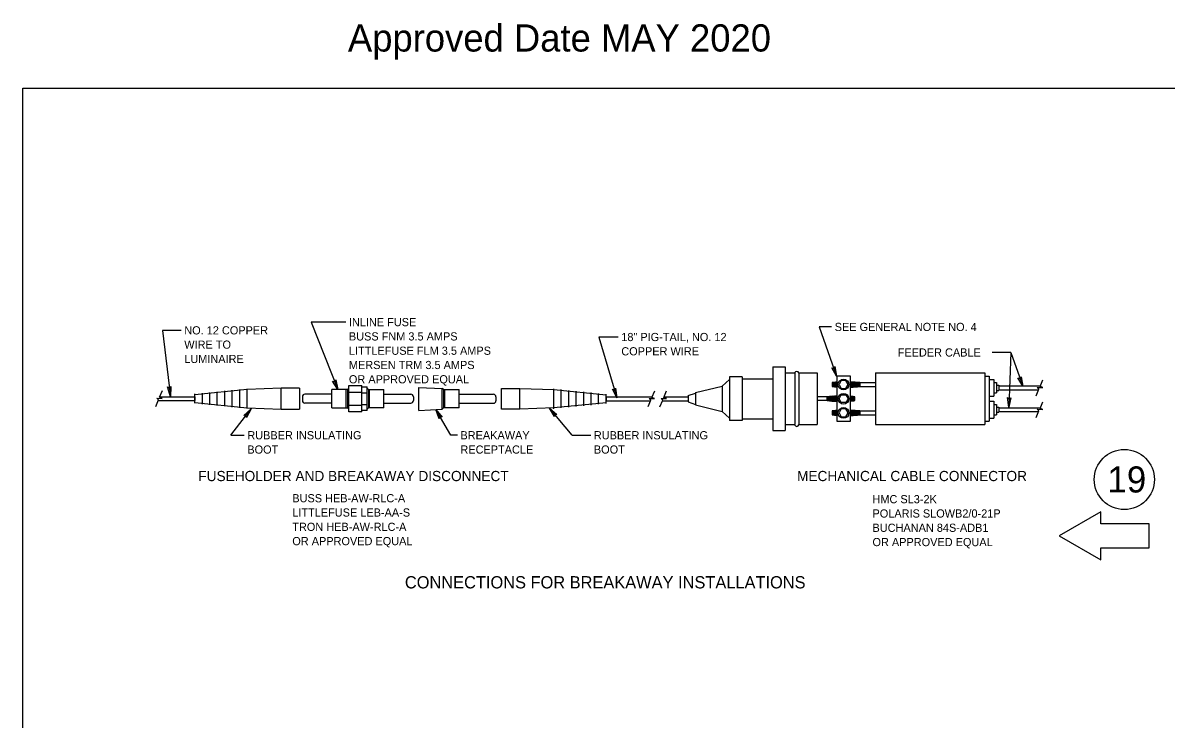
# Model space of a CAD drawing. Extents: x 99981 to 128681, y 99783 to 102182.
# Drawn here: x 125481 to 127161, y 101159 to 102182 of the extents above; entities that cross this region are included whole.
import ezdxf

# ---------------------------------------------------------------- set-up
doc = ezdxf.new("R2010")
doc.units = 0
for name, color, linetype in [('Default', 7, 'Continuous'), ('Level 1', 7, 'Continuous'), ('RD Lighting', 7, 'Continuous'), ('RD Standard Plans Active', 7, 'Continuous')]:
    doc.layers.add(name, color=color, linetype=linetype)

msp = doc.modelspace()

# ---------------------------------------------------------------- linework, layer by layer
at = {"layer": 'Default'}
msp.add_lwpolyline([(125481.4, 102086.3), (128681.1, 102086.3), (128681.1, 99886.7), (125481.4, 99886.7)], close=True, dxfattribs=at)
at = {"layer": 'Level 1'}
for p, q in [((125714, 101730.5), (125686.4, 101730.5)), ((125686.4, 101730.5), (125698.1, 101633)), ((125955.8, 101742.6), (125904.9, 101742.6)), ((125904.9, 101742.6), (125943.8, 101643.6)), ((126669.3, 101735.5), (126650.8, 101735.5)), ((126650.8, 101735.5), (126676.4, 101663.1)), ((126327.6, 101720.7), (126353.7, 101631.4)), ((126355.9, 101720.7), (126327.6, 101720.7)), ((126932.4, 101698), (126905, 101698)), ((126932.4, 101698), (126929.8, 101617.4)), ((126932.4, 101698), (126949.9, 101648.3)), ((126519.2, 101662), (126519.2, 101598.1)), ((126537.9, 101662), (126519.2, 101662)), ((126537.9, 101662), (126537.9, 101598.1)), ((126583, 101676.7), (126583, 101583.4)), ((126583, 101676.7), (126600.8, 101676.7)), ((126600.8, 101676.7), (126600.8, 101583.4)), ((126600.8, 101667.9), (126615, 101667.9)), ((126615, 101667.9), (126615, 101592.2)), ((126621, 101667.9), (126621, 101592.2)), ((126621, 101667.9), (126648.1, 101667.9)), ((126648.1, 101667.9), (126648.1, 101592.2)), ((126733.5, 101667.9), (126894.3, 101667.9)), ((126733.5, 101667.9), (126733.5, 101592.2)), ((126894.3, 101667.9), (126894.3, 101592.2)), ((126894.3, 101663.2), (126900.9, 101663.2)), ((126900.9, 101663.2), (126900.9, 101596.9)), ((125860.8, 101645.5), (125810.9, 101643.6)), ((125810.9, 101615.6), (125810.9, 101644.8)), ((125860.8, 101614.8), (125860.8, 101645.5)), ((125887.7, 101645.5), (125860.8, 101645.5)), ((125887.7, 101645.5), (125887.7, 101614.8)), ((125958.1, 101643.7), (125960, 101645.5)), ((125960, 101611), (125960, 101649.4)), ((125960, 101649.4), (125979.2, 101649.4)), ((125960, 101614.8), (125960, 101645.5)), ((125979.2, 101611), (125979.2, 101649.4)), ((125979.2, 101612.9), (125979.2, 101647.5)), ((125979.2, 101647.5), (125986.9, 101647.5)), ((125986.9, 101612.9), (125986.9, 101647.5)), ((125988.8, 101643.7), (125986.9, 101645.5)), ((126062.8, 101646.3), (126097.4, 101645.3)), ((126062.8, 101612.7), (126062.8, 101646.3)), ((126097.4, 101614.6), (126097.4, 101645.3)), ((126099.3, 101643.4), (126097.4, 101645.3)), ((126184.3, 101614.6), (126184.3, 101645.3)), ((126184.3, 101645.3), (126211.2, 101645.3)), ((126211.2, 101614.5), (126211.2, 101645.3)), ((126211.2, 101645.3), (126261.2, 101643.4)), ((126261.2, 101615.3), (126261.2, 101644.5)), ((126469.2, 101639.2), (126508.7, 101648.7)), ((126508.7, 101648.7), (126519.2, 101658.3)), ((126508.7, 101648.7), (126508.7, 101611.4)), ((126537.9, 101659.5), (126582.6, 101659.5)), ((126670.1, 101653.7), (126670.1, 101648)), ((126710.8, 101653.7), (126710.8, 101648)), ((126710.8, 101653.7), (126733.6, 101653.7)), ((126710.8, 101648), (126733.6, 101648)), ((126900.9, 101658.4), (126907.6, 101658.4)), ((126907.6, 101658.4), (126907.6, 101633.8)), ((126907.6, 101653.7), (126911.3, 101653.7)), ((126911.3, 101653.7), (126911.3, 101638.6)), ((126911.3, 101649.9), (126915.1, 101649.9)), ((126915.1, 101649.9), (126915.1, 101642.3)), ((126915.1, 101649), (126975.8, 101649)), ((126973.8, 101644.2), (126971.4, 101646.7)), ((126971.4, 101646.7), (126979.3, 101646.4)), ((126975.4, 101648.1), (126979.5, 101657.8)), ((126979.3, 101646.4), (126975.4, 101648.1)), ((125676.6, 101618.6), (125680.6, 101628.3)), ((125680.6, 101628.3), (125678.2, 101630.8)), ((125678.2, 101630.8), (125686.1, 101630.5)), ((125682.2, 101632.2), (125686.3, 101641.9)), ((125686.1, 101630.5), (125682.2, 101632.2)), ((125682.6, 101633), (125734.1, 101633)), ((125810.9, 101643.6), (125734.1, 101635.9)), ((125734.1, 101623.3), (125734.1, 101637.1)), ((125734.1, 101633), (125734.1, 101627.3)), ((125734.1, 101627.3), (125734.1, 101633)), ((125745, 101622.1), (125745, 101638.2)), ((125756, 101621.1), (125756, 101639.3)), ((125767, 101620), (125767, 101640.4)), ((125777.9, 101618.9), (125777.9, 101641.5)), ((125788.9, 101617.8), (125788.9, 101642.6)), ((125799.9, 101616.7), (125799.9, 101643.6)), ((125891.9, 101633), (125891.9, 101627.3)), ((125935.3, 101636.8), (125895.7, 101636.8)), ((125956.1, 101643.7), (125935.3, 101643.6)), ((125935.3, 101616.7), (125935.3, 101643.6)), ((125958.1, 101643.7), (125956.1, 101643.7)), ((125956.1, 101616.7), (125956.1, 101643.7)), ((125958.1, 101643.7), (125958.1, 101616.7)), ((125960, 101639.8), (125979.2, 101639.8)), ((125979.2, 101638.8), (125986.9, 101638.8)), ((125988.8, 101643.7), (125990.7, 101643.7)), ((125988.8, 101643.7), (125988.8, 101616.7)), ((125990.7, 101616.7), (125990.7, 101643.7)), ((125990.7, 101643.7), (126011.5, 101643.6)), ((126011.5, 101616.7), (126011.5, 101643.6)), ((126011.5, 101636.8), (126051.2, 101636.8)), ((126055, 101633), (126055, 101627.3)), ((126099.3, 101643.4), (126101.2, 101643.4)), ((126099.3, 101643.4), (126099.3, 101616.5)), ((126101.2, 101616.5), (126101.2, 101643.4)), ((126101.2, 101643.4), (126122, 101643.4)), ((126122, 101616.5), (126122, 101643.4)), ((126122, 101636.5), (126172.4, 101636.5)), ((126176.2, 101632.8), (126176.2, 101627.1)), ((126261.2, 101643.4), (126338, 101635.7)), ((126272.1, 101616.5), (126272.1, 101643.4)), ((126283.1, 101617.5), (126283.1, 101642.3)), ((126294.1, 101618.6), (126294.1, 101641.2)), ((126305.1, 101619.7), (126305.1, 101640.2)), ((126316, 101620.8), (126316, 101639)), ((126327, 101621.9), (126327, 101637.9)), ((126338, 101623), (126338, 101636.9)), ((126338, 101632.8), (126338, 101627.1)), ((126338, 101632.8), (126405.7, 101632.8)), ((126399.7, 101618.4), (126403.8, 101628.1)), ((126403.8, 101628.1), (126401.4, 101630.6)), ((126401.4, 101630.6), (126409.3, 101630.2)), ((126405.4, 101632), (126409.4, 101641.7)), ((126409.3, 101630.2), (126405.4, 101632)), ((126417.1, 101618.3), (126421.2, 101628)), ((126421.2, 101628), (126418.8, 101630.5)), ((126418.8, 101630.5), (126426.6, 101630.2)), ((126422.8, 101631.9), (126426.8, 101641.6)), ((126426.6, 101630.2), (126422.8, 101631.9)), ((126423.1, 101632.8), (126458.8, 101632.8)), ((126458.8, 101634.7), (126469.3, 101638.3)), ((126458.8, 101634.7), (126458.8, 101625.4)), ((126469.2, 101639.2), (126469.2, 101620.9)), ((126662.8, 101632.9), (126648.1, 101632.9)), ((126662.8, 101627.2), (126662.8, 101632.9)), ((126703.5, 101627.2), (126703.5, 101632.9)), ((126900.9, 101633.8), (126907.6, 101633.8)), ((126907.6, 101638.6), (126911.3, 101638.6)), ((126911.3, 101642.3), (126915.1, 101642.3)), ((126915.1, 101643.3), (126973.4, 101643.3)), ((126969.8, 101634.5), (126973.8, 101644.2)), ((125680.2, 101627.3), (125734.1, 101627.3)), ((125734.1, 101624.4), (125810.9, 101616.7)), ((125787, 101576.4), (125816.5, 101615.1)), ((125810.9, 101616.7), (125860.8, 101614.8)), ((125860.8, 101614.8), (125887.7, 101614.8)), ((125935.3, 101623.5), (125895.7, 101623.5)), ((125935.3, 101616.7), (125956.1, 101616.7)), ((125956.1, 101616.7), (125958.1, 101616.7)), ((125960, 101614.8), (125958.1, 101616.7)), ((125960, 101620.6), (125979.2, 101620.6)), ((125979.2, 101611), (125960, 101611)), ((125979.2, 101621.5), (125986.9, 101621.5)), ((125986.9, 101612.9), (125979.2, 101612.9)), ((125986.9, 101614.8), (125988.8, 101616.7)), ((125990.7, 101616.7), (125988.8, 101616.7)), ((126011.5, 101616.7), (125990.7, 101616.7)), ((126011.5, 101623.5), (126051.2, 101623.5)), ((126062.8, 101612.7), (126097.4, 101614.6)), ((126110.1, 101576.4), (126087.8, 101614.1)), ((126097.4, 101614.6), (126099.3, 101616.5)), ((126101.2, 101616.5), (126099.3, 101616.5)), ((126122, 101616.5), (126101.2, 101616.5)), ((126122, 101623.3), (126172.4, 101623.3)), ((126211.2, 101614.5), (126184.3, 101614.6)), ((126261.2, 101616.5), (126211.2, 101614.5)), ((126288.2, 101576.4), (126255, 101616.3)), ((126338, 101624.2), (126261.2, 101616.5)), ((126338, 101627.1), (126403.4, 101627.1)), ((126420.8, 101627.1), (126458.8, 101627.1)), ((126458.8, 101625.4), (126469.3, 101621.7)), ((126469.2, 101620.9), (126508.7, 101611.4)), ((126508.7, 101611.4), (126519.2, 101601.5)), ((126662.8, 101627.2), (126648.1, 101627.2)), ((126670.1, 101612.1), (126670.1, 101606.4)), ((126710.8, 101612.1), (126710.8, 101606.4)), ((126710.8, 101612.1), (126733.6, 101612.1)), ((126900.9, 101626.3), (126907.6, 101626.3)), ((126907.6, 101626.3), (126907.6, 101601.7)), ((126907.6, 101621.5), (126911.3, 101621.5)), ((126911.3, 101621.5), (126911.3, 101606.4)), ((126911.3, 101617.7), (126915.1, 101617.7)), ((126915.1, 101617.7), (126915.1, 101610.2)), ((126915.1, 101616.8), (126975.8, 101616.8)), ((126915.1, 101611.1), (126973.4, 101611.1)), ((126969.8, 101602.4), (126973.8, 101612.1)), ((126973.8, 101612.1), (126971.4, 101614.6)), ((126971.4, 101614.6), (126979.3, 101614.2)), ((126975.4, 101615.9), (126979.5, 101625.6)), ((126979.3, 101614.2), (126975.4, 101615.9)), ((126537.9, 101598.1), (126519.2, 101598.1)), ((126537.9, 101600.6), (126582.6, 101600.6)), ((126710.8, 101606.4), (126733.6, 101606.4)), ((126894.3, 101596.9), (126900.9, 101596.9)), ((126900.9, 101601.7), (126907.6, 101601.7)), ((126907.6, 101606.4), (126911.3, 101606.4)), ((126911.3, 101610.2), (126915.1, 101610.2)), ((126583, 101583.4), (126600.8, 101583.4)), ((126600.8, 101592.2), (126615, 101592.2)), ((126621, 101592.2), (126648.1, 101592.2)), ((126733.5, 101592.2), (126894.3, 101592.2)), ((125787, 101576.4), (125806.6, 101576.4)), ((126119.6, 101576.4), (126110.1, 101576.4)), ((126288.2, 101576.4), (126315.6, 101576.4))]:
    msp.add_line(p, q, dxfattribs=at)
for points in [[(126674, 101677.2), (126676.4, 101663.1), (126669.5, 101675.6), (126672.4, 101674.3)], [(126676.7, 101596.9), (126696.9, 101596.9), (126696.9, 101663.2), (126676.7, 101663.2)], [(126947.5, 101662.4), (126949.9, 101648.3), (126943, 101660.8), (126946, 101659.5)], [(125698.8, 101648.1), (125698.1, 101633), (125693.8, 101647.5), (125696.6, 101645.5)], [(125940.9, 101657.6), (125943.8, 101643.6), (125936.4, 101655.9), (125939.5, 101654.7)], [(126352, 101645.6), (126353.7, 101631.4), (126347.4, 101644.2), (126350.3, 101642.8)], [(126693.4, 101650.9), (126690.1, 101656.6), (126683.5, 101656.6), (126680.2, 101650.9), (126683.5, 101645.1), (126690.1, 101645.1)], [(126680.2, 101630), (126683.5, 101635.8), (126690.1, 101635.8), (126693.4, 101630), (126690.1, 101624.3), (126683.5, 101624.3)], [(126932.6, 101631.4), (126929.8, 101617.4), (126927.8, 101631.6), (126930.1, 101629.3)], [(125806.1, 101605.4), (125816.5, 101615.1), (125809.9, 101602.5), (125809.3, 101605.7)], [(126092.9, 101600.7), (126087.8, 101614.1), (126097, 101603.1), (126093.8, 101603.8)], [(126262.2, 101603.9), (126255, 101616.3), (126265.9, 101606.9), (126262.6, 101607.1)], [(126693.4, 101609.2), (126690.1, 101615), (126683.5, 101615), (126680.2, 101609.2), (126683.5, 101603.5), (126690.1, 101603.5)]]:
    msp.add_lwpolyline(points, close=True, dxfattribs=at)
for centre in [(126686.8, 101650.9), (126686.8, 101630), (126686.8, 101609.2)]:
    msp.add_circle(centre, 7.87, dxfattribs=at)
for centre, radius, start, end in [((126618, 101667.1), 3.13, 13.8187, 166.1813), ((126683.9, 101681), 35.3, 246.9234, 250.0588), ((126690.5, 101472.2), 182.6, 94.3078, 96.3947), ((126683.9, 101681), 34.2, 246.2968, 257.7799), ((126690.5, 101829.5), 182.6, 263.6053, 265.6922), ((126683.9, 101681), 31.3, 244.0184, 256.695), ((126683.9, 101681), 32.1, 244.8289, 257.172), ((126683.9, 101681), 32.9, 245.3688, 257.4424), ((126683.9, 101681), 33.5, 245.8941, 257.5753), ((126683.9, 101681), 34.8, 246.798, 253.7631), ((126683.9, 101681), 30.6, 243.617, 256.3872), ((126683.9, 101681), 30, 245.4513, 256.2262), ((126683.9, 101681), 29.3, 247.3871, 255.8534), ((126683.9, 101681), 28.7, 249.6525, 255.6032), ((126710.5, 101680.8), 34.2, 246.2968, 258.5078), ((126690.5, 101472.2), 182.6, 83.6053, 87.9783), ((126710.5, 101680.8), 31.9, 244.725, 270.432), ((126710.5, 101680.8), 33.4, 245.9109, 263.6185), ((126710.5, 101680.8), 34.8, 246.8841, 255.1625), ((126710.5, 101680.8), 35.4, 247.2896, 252.3204), ((126690.5, 101829.5), 182.6, 272.0217, 276.3947), ((126710.5, 101680.8), 36, 247.6656, 249.8244), ((126710.5, 101680.8), 30.1, 243.205, 270.432), ((126710.5, 101680.8), 31, 244.1545, 270.432), ((126710.5, 101680.8), 32.8, 245.5356, 270.432), ((126710.5, 101680.8), 29.2, 244.3604, 270.432), ((126710.5, 101680.8), 28.5, 246.8058, 270.432), ((126710.5, 101680.8), 27.9, 250.4487, 270.432), ((126710.5, 101680.8), 27.2, 257.6483, 270.432), ((125895.7, 101633), 3.78, 90, 180), ((126051.2, 101633), 3.78, 0, 90), ((126172.4, 101632.8), 3.78, 0, 90), ((126683.2, 101451.4), 182.6, 92.0217, 96.3947), ((126663.1, 101600.1), 32.8, 65.5356, 90.432), ((126663.1, 101600.1), 31.9, 64.725, 90.432), ((126663.1, 101600.1), 31, 64.1545, 90.432), ((126663.1, 101600.1), 30.1, 63.205, 90.432), ((126663.1, 101600.1), 29.2, 64.3604, 90.432), ((126663.1, 101600.1), 28.5, 66.8058, 90.432), ((126663.1, 101600.1), 27.9, 70.4487, 90.432), ((126663.1, 101600.1), 33.4, 65.9109, 83.6185), ((126663.1, 101600.1), 34.2, 66.2968, 78.5078), ((126663.1, 101600.1), 34.8, 66.8841, 75.1625), ((126663.1, 101600.1), 35.4, 67.2896, 72.3204), ((126663.1, 101600.1), 36, 67.6656, 69.8244), ((126683.2, 101451.4), 182.6, 83.6053, 85.6922), ((126689.7, 101599.9), 33.5, 65.8941, 77.5753), ((126689.7, 101599.9), 32.9, 65.3688, 77.4424), ((126689.7, 101599.9), 32.1, 64.8289, 77.172), ((126689.7, 101599.9), 31.3, 64.0184, 76.695), ((126689.7, 101599.9), 30.6, 63.617, 76.3872), ((126689.7, 101599.9), 30, 65.4513, 76.2262), ((126689.7, 101599.9), 29.3, 67.3871, 75.8534), ((126689.7, 101599.9), 28.7, 69.6525, 75.6032), ((126689.7, 101599.9), 34.2, 66.2968, 77.7799), ((126689.7, 101599.9), 34.8, 66.798, 73.7631), ((126689.7, 101599.9), 35.3, 66.9234, 70.0588), ((125895.7, 101627.3), 3.78, 180, 270), ((126051.2, 101627.3), 3.78, 270, 360), ((126172.4, 101627.1), 3.78, 270, 360), ((126683.2, 101808.7), 182.6, 263.6053, 267.9783), ((126663.1, 101600.1), 27.2, 77.6484, 90.432), ((126690.5, 101430.6), 182.6, 94.3078, 96.3947), ((126683.9, 101639.4), 31.3, 244.0184, 256.695), ((126683.9, 101639.4), 30.6, 243.617, 256.3872), ((126683.9, 101639.4), 30, 245.4513, 256.2262), ((126683.9, 101639.4), 29.3, 247.3871, 255.8534), ((126683.9, 101639.4), 28.7, 249.6525, 255.6032), ((126683.2, 101808.7), 182.6, 274.3078, 276.3947), ((126690.5, 101430.6), 182.6, 83.6053, 87.9783), ((126710.5, 101639.2), 30.1, 243.205, 270.432), ((126710.5, 101639.2), 31, 244.1545, 270.432), ((126710.5, 101639.2), 29.2, 244.3604, 270.432), ((126710.5, 101639.2), 28.5, 246.8058, 270.432), ((126710.5, 101639.2), 27.9, 250.4487, 270.432), ((126710.5, 101639.2), 27.2, 257.6483, 270.432), ((126683.9, 101639.4), 35.3, 246.9234, 250.0588), ((126683.9, 101639.4), 34.2, 246.2968, 257.7799), ((126690.5, 101787.9), 182.6, 263.6053, 265.6922), ((126683.9, 101639.4), 32.1, 244.8289, 257.172), ((126683.9, 101639.4), 32.9, 245.3688, 257.4424), ((126683.9, 101639.4), 33.5, 245.8941, 257.5753), ((126683.9, 101639.4), 34.8, 246.798, 253.7631), ((126710.5, 101639.2), 34.2, 246.2968, 258.5078), ((126710.5, 101639.2), 31.9, 244.725, 270.432), ((126710.5, 101639.2), 33.4, 245.9109, 263.6185), ((126710.5, 101639.2), 34.8, 246.8841, 255.1625), ((126710.5, 101639.2), 35.4, 247.2896, 252.3204), ((126690.5, 101787.9), 182.6, 272.0217, 276.3947), ((126710.5, 101639.2), 36, 247.6656, 249.8244), ((126710.5, 101639.2), 32.8, 245.5356, 270.432), ((126618, 101592.5), 3.13, 193.8187, 346.1813)]:
    msp.add_arc(centre, radius, start, end, dxfattribs=at)
at = {"layer": 'RD Lighting'}
msp.add_lwpolyline([(127003.4, 101428.7), (127064.8, 101393.2), (127064.8, 101410.9), (127135.8, 101410.9), (127135.8, 101446.4), (127064.8, 101446.4), (127064.8, 101464.1)], close=True, dxfattribs=at)
msp.add_circle((127099.2, 101511.4), 44.2, dxfattribs=at)

# ---------------------------------------------------------------- texts
at = {"layer": 'Level 1'}
for s, height, p in [(' INLINE FUSE', 12, (125955.8, 101736.6)), (' NO. 12 COPPER ', 12, (125714, 101724.5)), (' SEE GENERAL NOTE NO. 4', 12, (126669.3, 101729.5)), (' WIRE TO ', 12, (125714, 101703.5)), (' BUSS FNM 3.5 AMPS', 12, (125955.8, 101715.6)), (' 18" PIG-TAIL, NO. 12', 12, (126355.9, 101714.7)), (' LITTLEFUSE FLM 3.5 AMPS', 12, (125955.8, 101694.6)), (' COPPER WIRE', 12, (126355.9, 101693.7)), ('FEEDER CABLE ', 12, (126766.3, 101692)), (' LUMINAIRE', 12, (125714, 101682.5)), (' MERSEN TRM 3.5 AMPS', 12, (125955.8, 101673.6)), (' OR APPROVED EQUAL', 12, (125955.8, 101652.6)), (' RUBBER INSULATING', 12, (125806.6, 101570.4)), (' BREAKAWAY', 12, (126119.6, 101570.4)), (' RUBBER INSULATING', 12, (126315.6, 101570.4)), (' BOOT', 12, (125806.6, 101549.4)), (' RECEPTACLE', 12, (126119.6, 101549.4)), (' BOOT', 12, (126315.6, 101549.4)), ('FUSEHOLDER AND BREAKAWAY DISCONNECT', 15, (125739.1, 101509)), ('MECHANICAL CABLE CONNECTOR', 15, (126618.5, 101509)), ('BUSS HEB-AW-RLC-A', 12, (125877.1, 101477.9)), ('HMC SL3-2K', 12, (126729.3, 101476.5)), ('LITTLEFUSE LEB-AA-S', 12, (125877.1, 101456.9)), ('POLARIS SLOWB2/0-21P', 12, (126729.3, 101455.5)), ('TRON HEB-AW-RLC-A', 12, (125877.1, 101435.9)), ('BUCHANAN 84S-ADB1 ', 12, (126729.3, 101434.5)), ('OR APPROVED EQUAL', 12, (125877.1, 101414.9)), ('OR APPROVED EQUAL', 12, (126729.3, 101413.5)), ('CONNECTIONS FOR BREAKAWAY INSTALLATIONS', 18, (126042.5, 101351.4))]:
    msp.add_text(s, height=height, dxfattribs=at).set_placement(p)
at = {"layer": 'RD Lighting'}
msp.add_text('19', height=38.31, dxfattribs=at).set_placement((127074.4, 101492.3))
at = {"layer": 'RD Standard Plans Active'}
msp.add_text('Approved Date MAY 2020', height=40, dxfattribs=at).set_placement((125958.8, 102140))

doc.saveas('drawing.dxf')
